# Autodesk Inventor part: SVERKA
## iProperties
Shininess: 64.0
Length Units: 11269
Angle Units: 11279
Time Units: 11290
Mass Units: 11283
Length Display Precision: 3
Angle Display Precision: 2
Compacted: True
Part Number: SVERKA
Document SubType Name: Modeling
Created: 2003-04
Material: Výchozí
Designer: rudolf_martonka
Density: 0.0
Volumn: 0.0
Area: 0.0
PropertySet Name: Model Information
Control State: 0
Master: False
Checked Out: False
Author: rudolf_martonka
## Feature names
1. Vysunutí1 [Extrusion]
2. Vysunutí2 [Extrusion]
3. Vysunutí3 [Extrusion]
4. Díra1 [Hole]
5. Díra2 [Hole]
